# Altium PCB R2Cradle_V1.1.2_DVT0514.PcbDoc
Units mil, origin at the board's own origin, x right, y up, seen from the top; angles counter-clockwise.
Board outline 1575.07 x 1575.04 mil, 4 copper layers (Top Layer, GND, POW, Bottom Layer), stack 127.647 mil thick; 53 components, 13 nets, 144 pads, 79 vias.
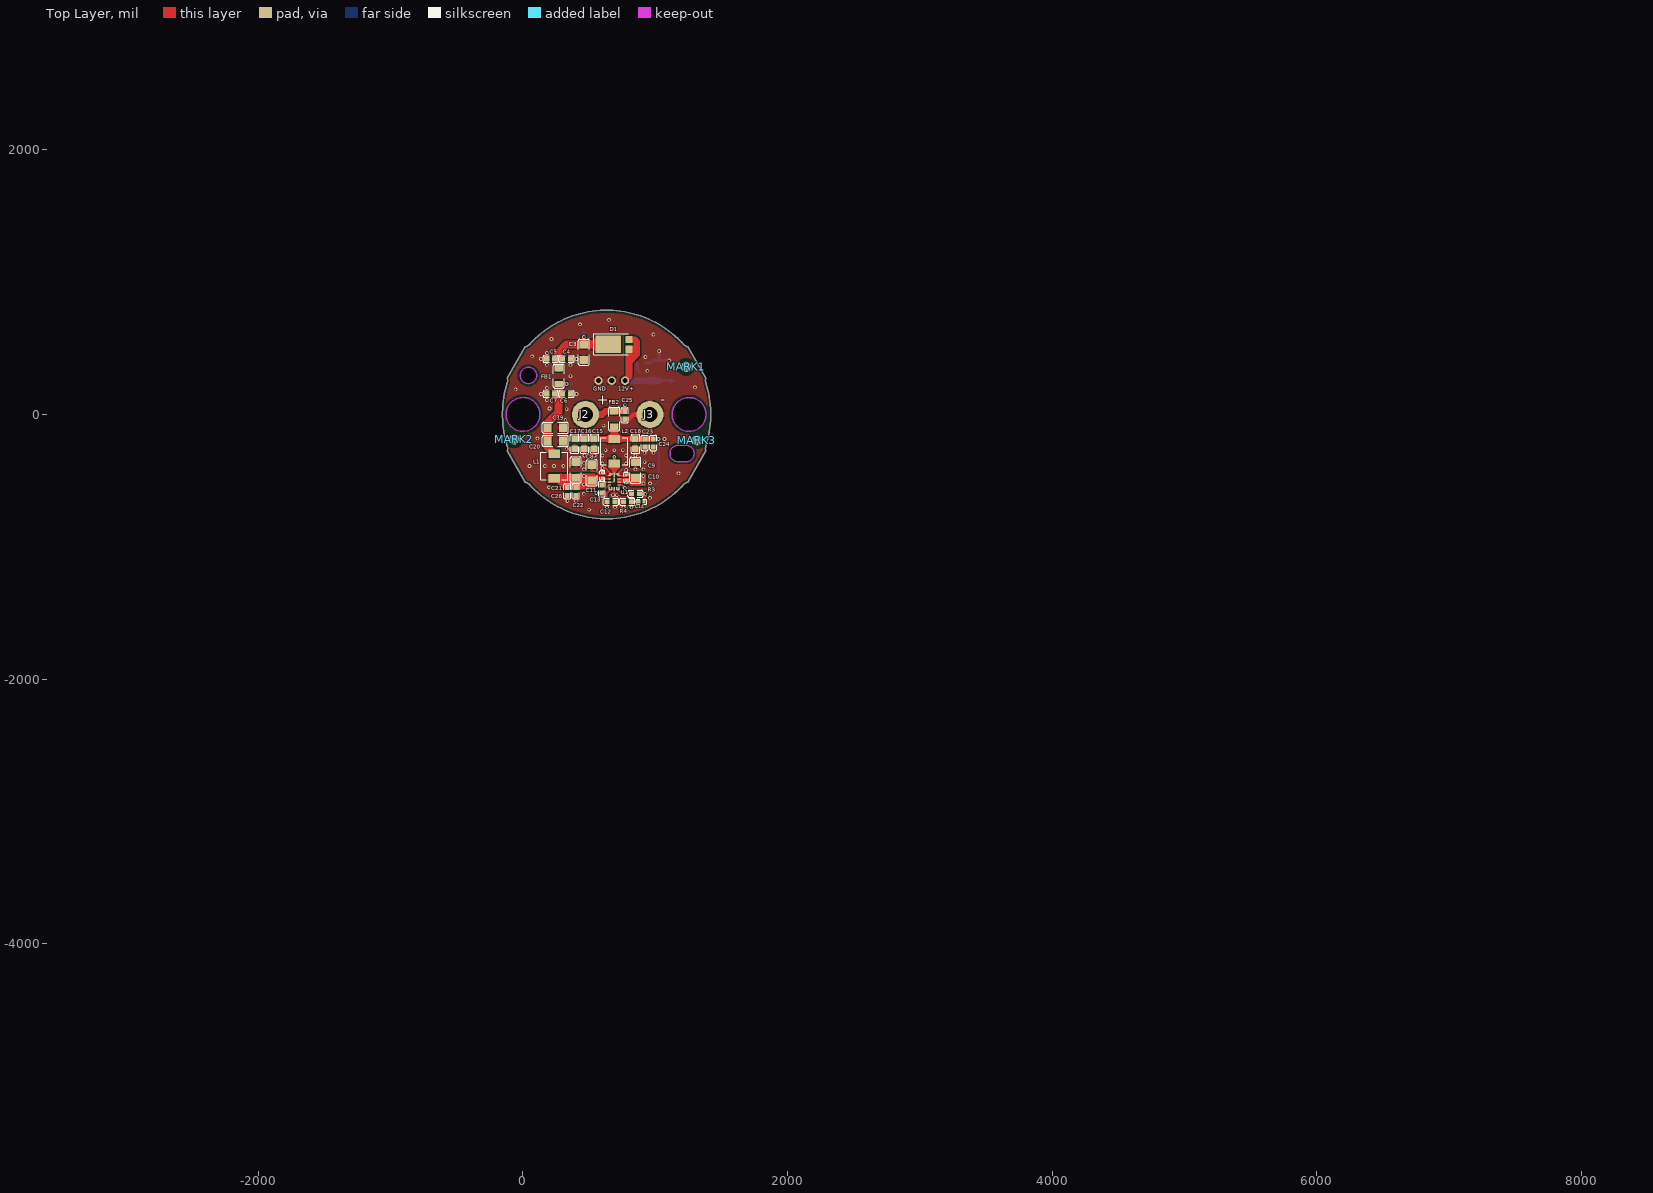
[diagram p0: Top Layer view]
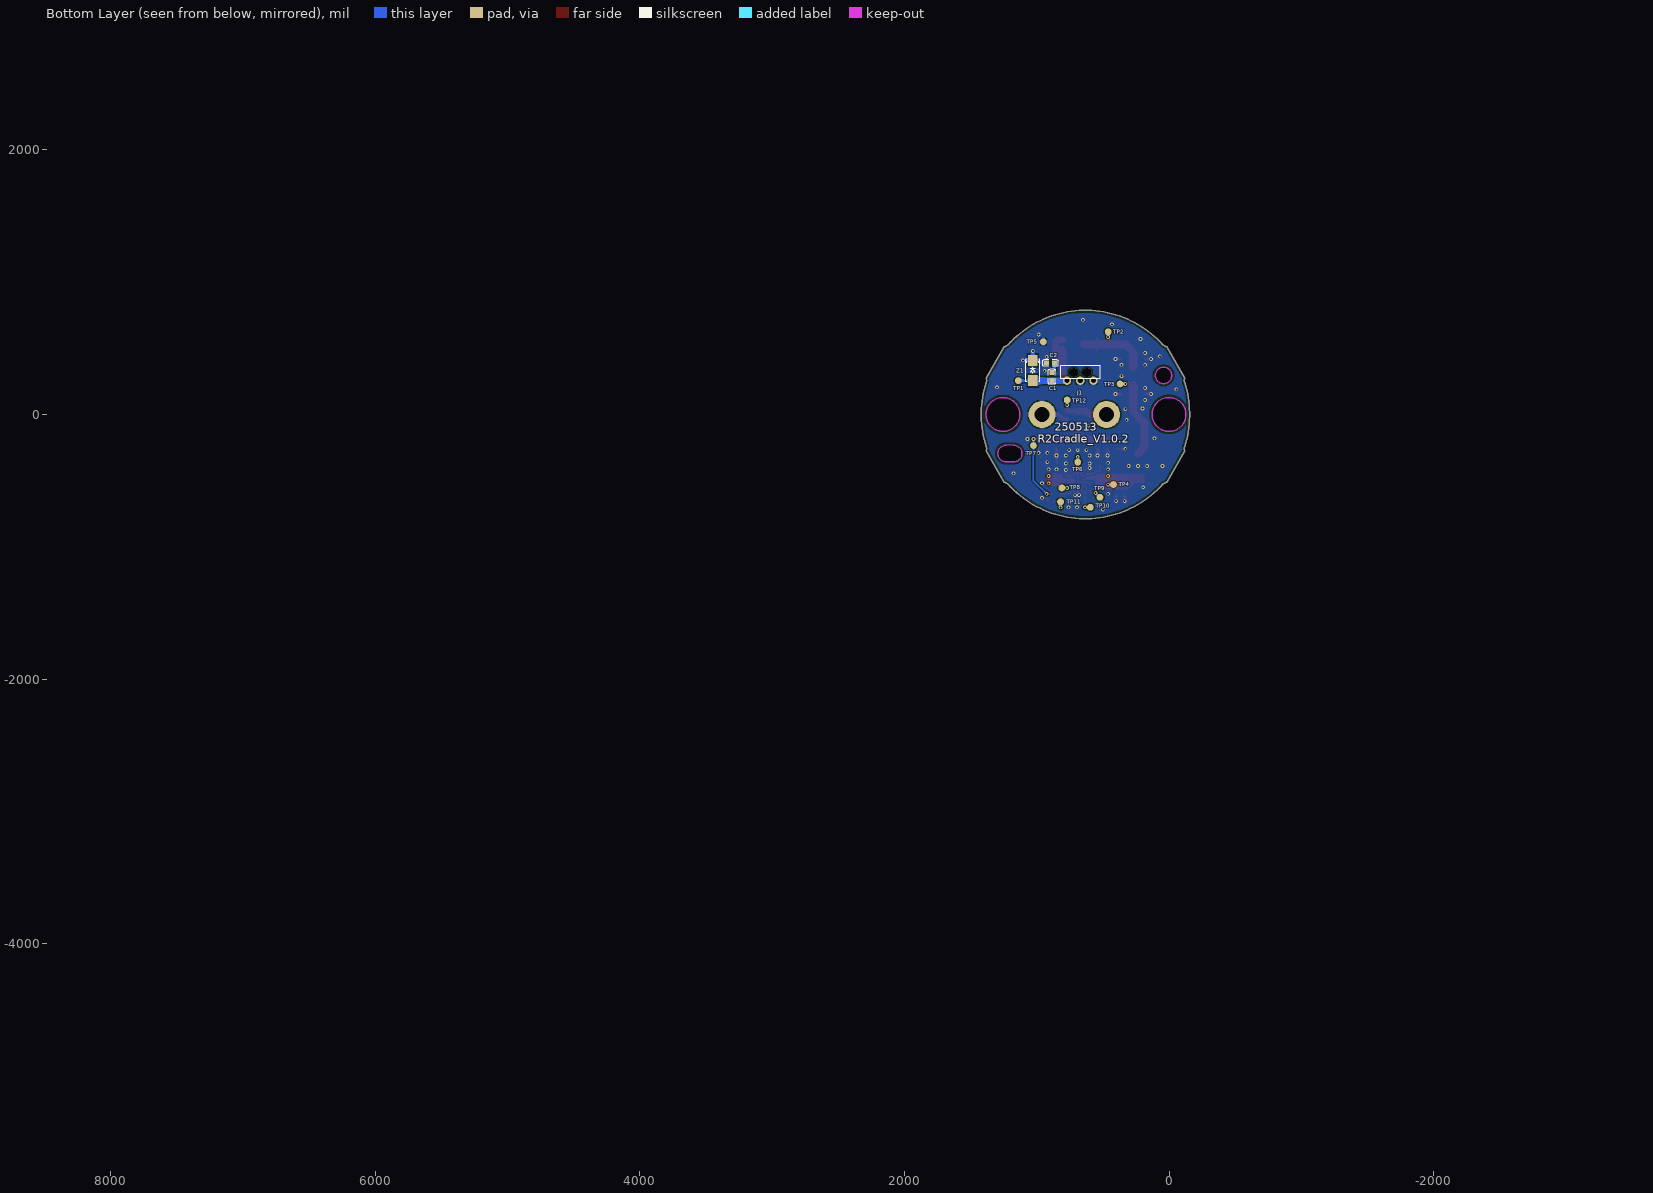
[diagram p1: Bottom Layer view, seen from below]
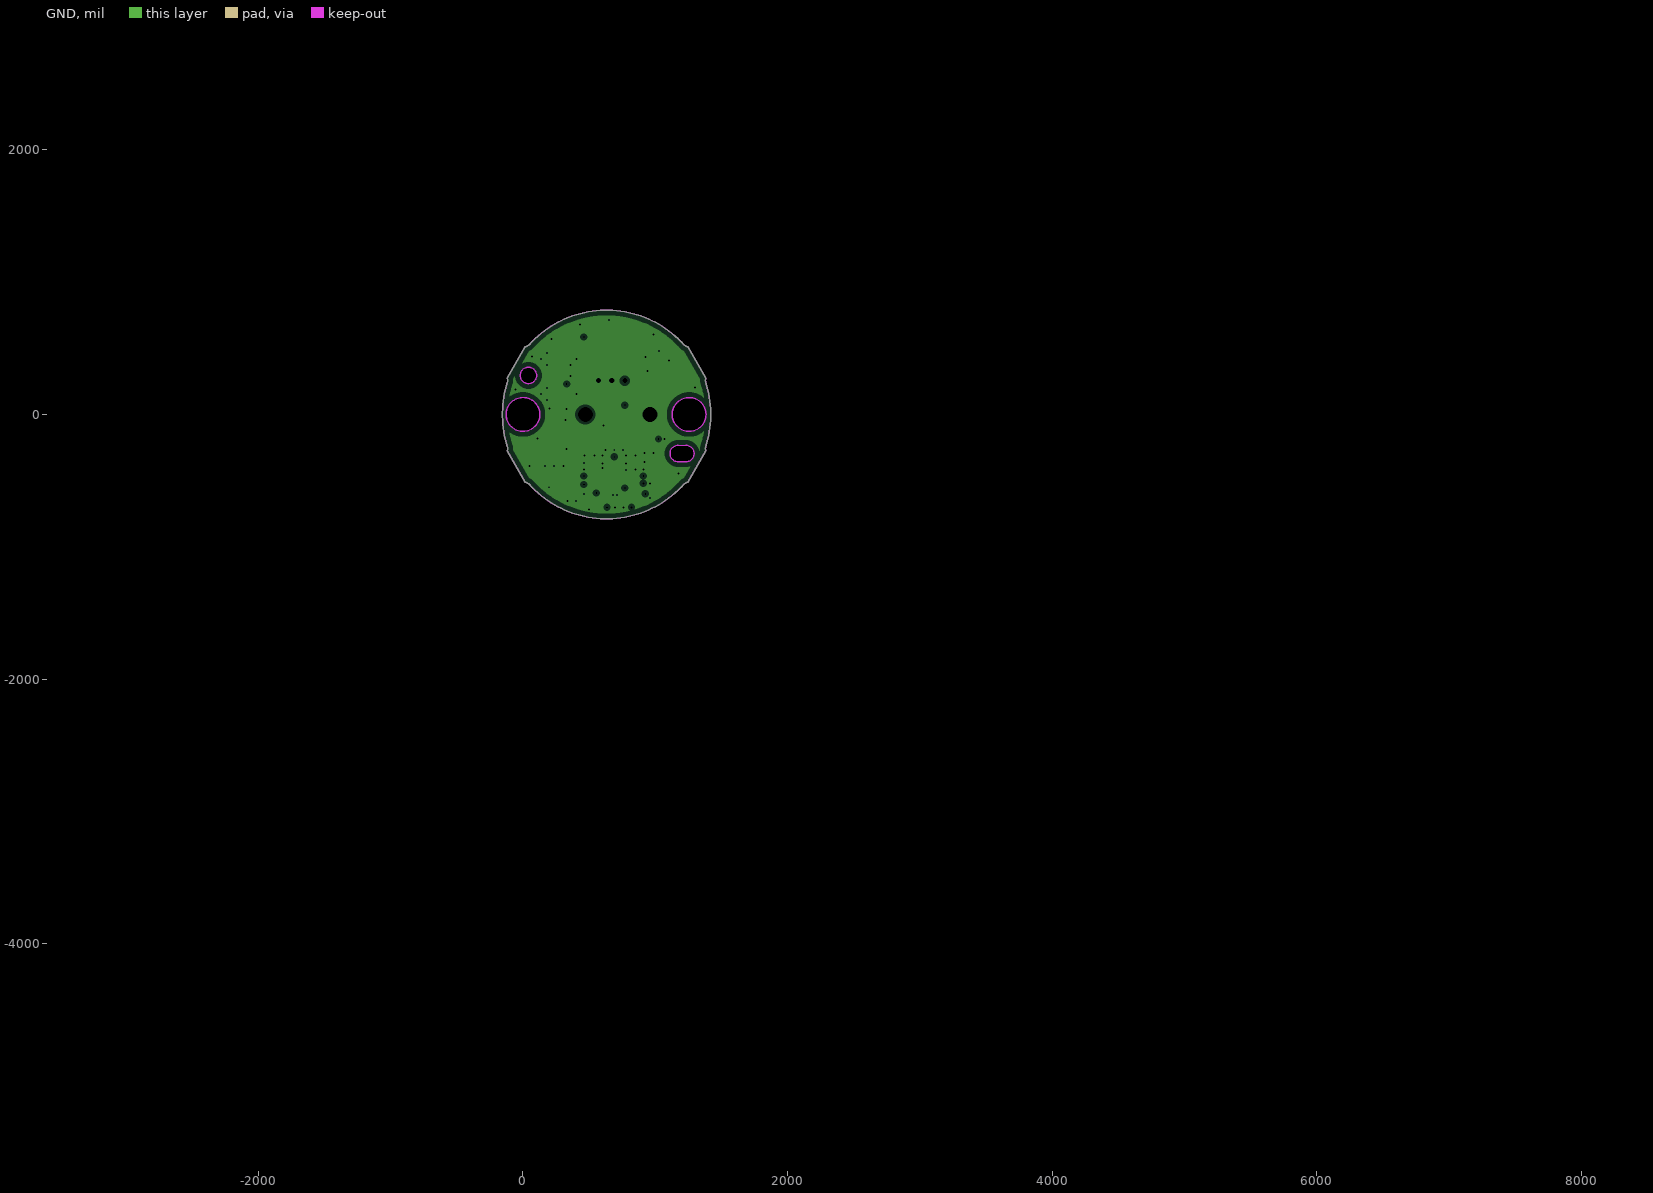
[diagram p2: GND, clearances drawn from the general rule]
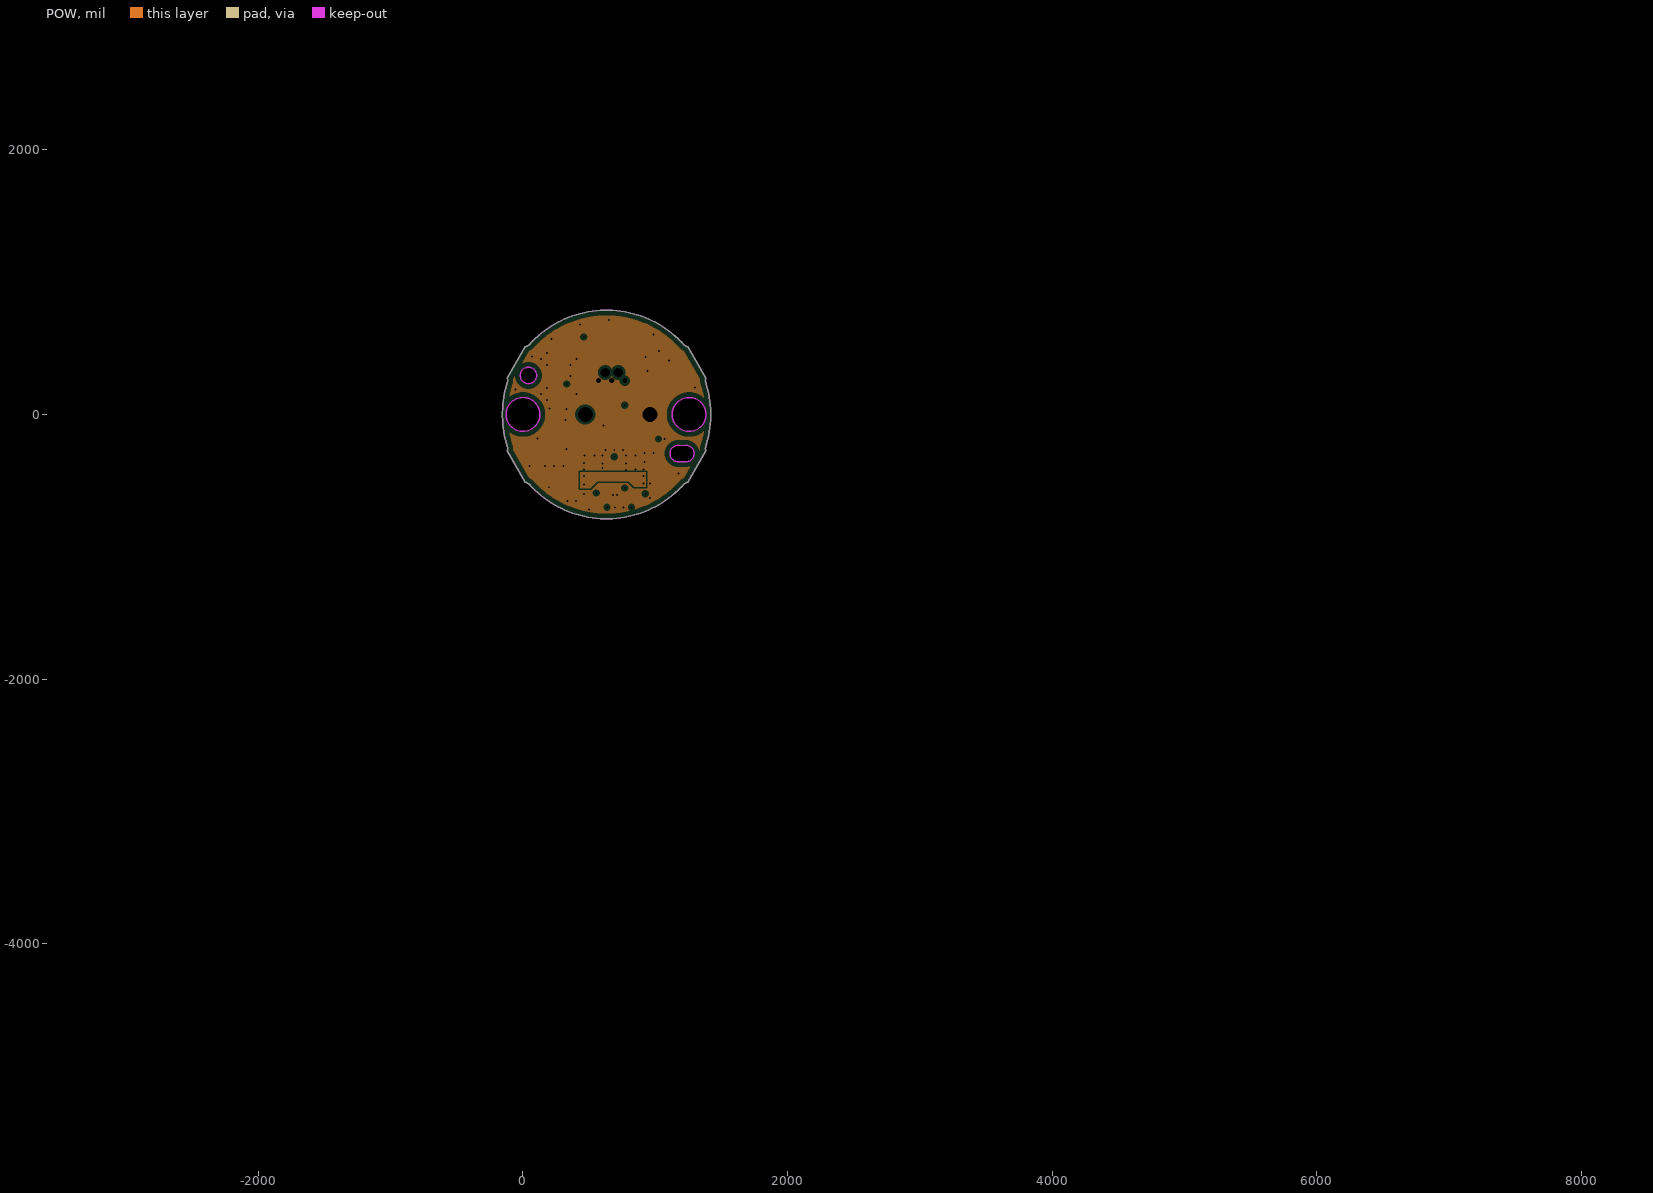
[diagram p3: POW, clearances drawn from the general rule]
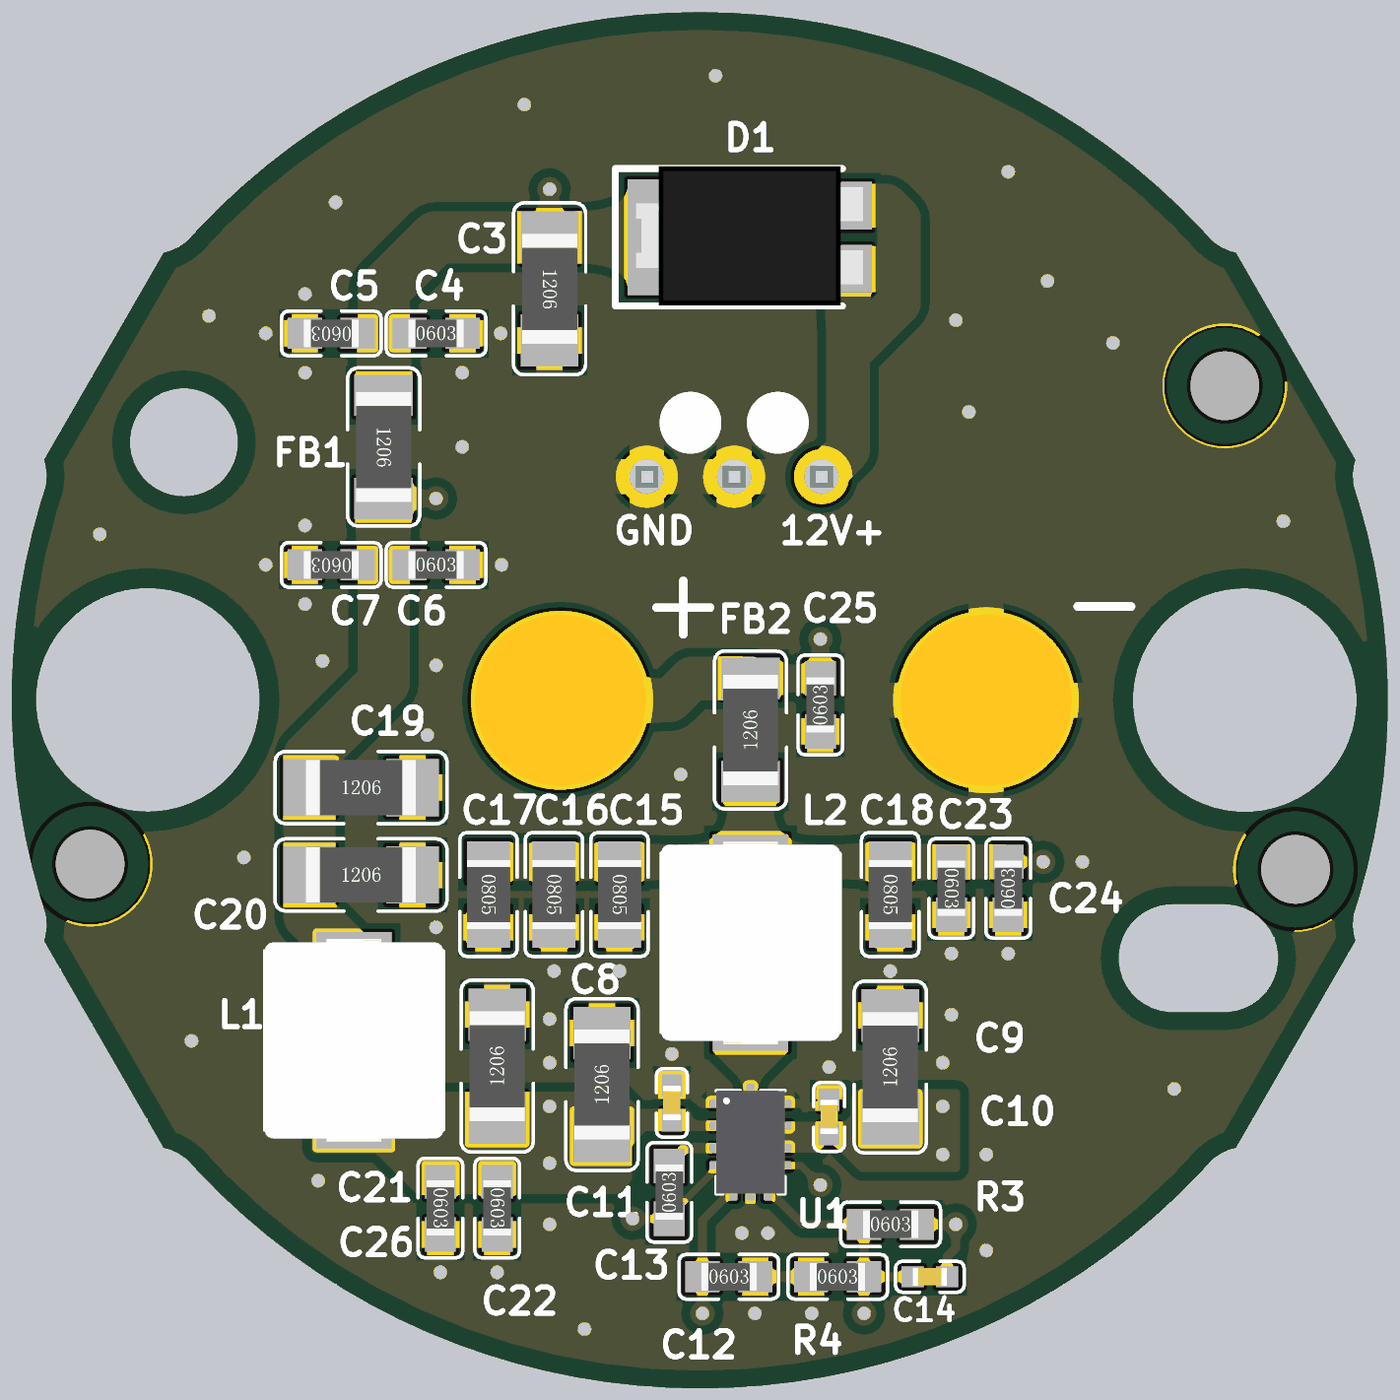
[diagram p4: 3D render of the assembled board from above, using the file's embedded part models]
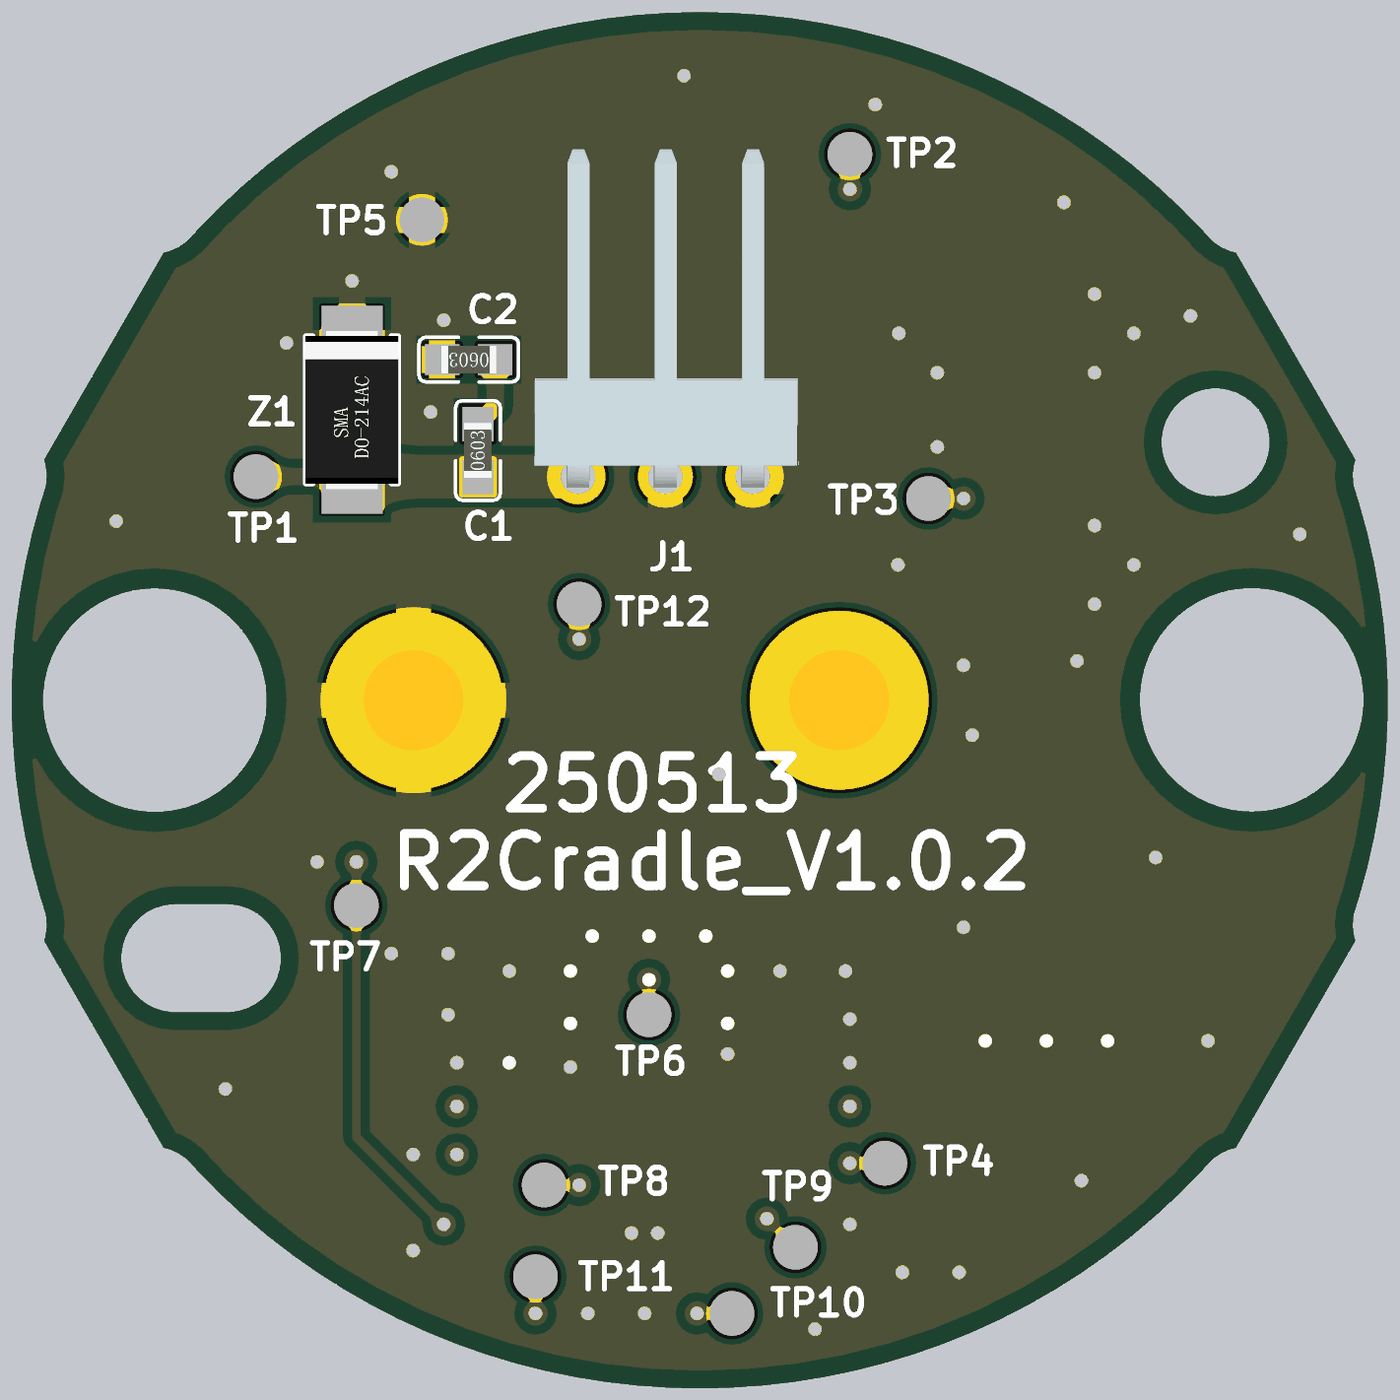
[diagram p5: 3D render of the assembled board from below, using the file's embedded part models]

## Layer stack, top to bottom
Top Solder: solder mask 0.5906, Solder Resist, Dk 3.5
Top Layer: signal copper 2.8
Dielectric 2: prepreg 5, PP-006, Dk 4.1
GND: plane copper 1.3778, net GND_POWER
Dielectric 1: dielectric 109.2913, FR-4, Dk 4.8
POW: plane copper 1.3778, net GND_POWER
Dielectric 3: prepreg 5, PP-006, Dk 4.1
Bottom Layer: signal copper 2.8
Bottom Solder: solder mask 0.5906, Solder Resist, Dk 3.5

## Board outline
-118.67,-275.32 cw(c-118.44,-275.18) -118.7,-275.1 ccw(c-174.55,-256.75) -117.49,-242.57 cw(c631.89,0) -117.49,242.57 ccw(c-174.55,256.75) -118.7,275.1 cw(c-118.44,275.18) -118.67,275.31 18.18,512.35 cw(c18.41,512.22) 18.35,512.48 ccw(c6.32,570.03) 47.13,527.7 cw(c631.89,0) 1216.66,527.7 ccw(c1257.47,570.02) 1245.41,512.48 cw(c1245.38,512.22) 1245.6,512.35 1382.43,275.36 cw(c1382.23,275.19) 1382.48,275.11 ccw(c1438.33,256.75) 1381.28,242.57 cw(c631.9,0) 1381.28,-242.57 ccw(c1438.34,-256.75) 1382.48,-275.09 cw(c1382.23,-275.18) 1382.46,-275.32 1245.6,-512.36 cw(c1245.37,-512.22) 1245.43,-512.48 ccw(c1257.46,-570.02) 1216.66,-527.7 cw(c631.89,0) 47.13,-527.7 ccw(c6.32,-570.02) 18.36,-512.48 cw(c18.41,-512.22) 18.18,-512.35
cut-out: 1173.23,-357.09 cw(c1173.23,-295.28) 1173.23,-233.46 1232.29,-233.46 cw(c1232.29,-295.28) 1232.29,-357.09
cut-out: 41.34,233.46 cw(c41.34,295.28) -20.47,295.28 cw(c41.34,295.28) 41.34,357.09 cw(c41.34,295.28) 103.15,295.28 cw(c41.34,295.28)
cut-out: 1255.81,-127.82 cw(c1255.81,0.13) 1127.86,0.13 cw(c1255.81,0.13) 1255.81,128.08 cw(c1255.81,0.13) 1383.76,0.13 cw(c1255.81,0.13)
cut-out: -0.02,-127.49 cw(c-0.02,0.46) -127.97,0.46 cw(c-0.02,0.46) -0.02,128.41 cw(c-0.02,0.46) 127.93,0.46 cw(c-0.02,0.46)

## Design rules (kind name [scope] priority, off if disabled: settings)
Clearance Clearance_1 [OnLayer('Keep-Out Layer')] p1: gap=10 ignorepadtopadclearanceinfootprint=FALSE except(20: Arc-Fill Arc-Poly Arc-Region Track-Fill Track-Poly Track-Region SMDPad-Fill SMDPad-Poly SMDPad-Region THPad-Fill THPad-Poly THPad-Region Via-Fill Via-Poly Via-Region Fill-Fill Fill-Poly Fill-Region Poly-Poly Poly-Region Region-Region)
Clearance [All] p2: gap=10 ignorepadtopadclearanceinfootprint=FALSE
HoleSize [All] p1: absolutevalues=TRUE maxlimit=200 minlimit=1 maxpercent=80.000 minpercent=20.000
HoleToHoleClearance [All] p1: gap=0 allowstackedmicrovias=TRUE
MinimumSolderMaskSliver [All] p1: minsoldermaskwidth=0
PlaneClearance [All] p1: clearance=20
PlaneConnect [All] p1: planeconnectstyle=Relief reliefexpansion=20 reliefentries=4 reliefconductorwidth=10 reliefairgap=10
PolygonConnect [All] p1: thpad.connectstyle=Relief thpad.reliefconductorwidth=40 thpad.reliefentries=4 thpad.polygonreliefangle="90 Angle" thpad.airgapwidth=10 smdpad.connectstyle=Relief smdpad.reliefconductorwidth=30 smdpad.reliefentries=4 smdpad.polygonreliefangle="90 Angle" smdpad.airgapwidth=10 via.connectstyle=Direct via.reliefconductorwidth=10 via.reliefentries=4 via.polygonreliefangle="90 Angle" via.airgapwidth=10
RoutingVias [All] p1: holewidth=11.81 width=23.62 viastyle="Through Hole" minholewidth=3.94 minwidth=15.75 maxholewidth=23.62 maxwidth=39.37
SilkToSilkClearance [All] p1: silktosilkclearance=0
SilkToSolderMaskClearance [IsPad] p1: minsilkscreentomaskgap=0 clearancetoexposedcopper=TRUE
SolderMaskExpansion [All] p1: expansion=4
Width [All] p1: maxlimit=100 minlimit=5 preferedwidth=10
23 further rules are at their usual default settings.

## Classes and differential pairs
component class R2Cradle_V0.1: C1 C2 C4 C6 C8 C12 C15 C16 C17 C18 C19 C20 C25 D1 J1 J2 J3 L1 L2 MARK1 MARK2 MARK3 R3 R4 TP1 TP2 TP3 TP4 TP5 TP6 TP7 TP8 TP9 TP10 TP11 Z1

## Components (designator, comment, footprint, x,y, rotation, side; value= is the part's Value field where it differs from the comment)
C1 "CAP NP" RC0603 885.83,286 r90 bottom value=103/0603
C2 "CAP NP" RC0603 896.31,390 r0 bottom value=103/0603 (schematic designator C11)
C3 "CAP NP" RC1206 460,470.94 r270 top value=475/1206 (schematic designator C4)
C4 "CAP NP" RC0603 330,420 r0 top value=104/0603 (schematic designator C3)
C5 "CAP NP" RC0603 210,420 r180 top value=104/0603 (schematic designator C3)
C6 "CAP NP" RC0603 330,155 r0 top value=104/0603
C7 "CAP NP" RC0603 210,155 r180 top value=104/0603 (schematic designator C6)
C8 "CAP NP" RC1206 520,-440 r90 top value=475/1206
C9 "CAP NP" RC1206 850,-420 r90 top value=475/1206
C10 "Comment" C0402 780,-477 r90 top
C11 "Comment" C0402 600,-461 r90 top
C12 "CAP NP" RC0603 665.31,-660 r0 top value=105/0603
C13 "CAP NP" RC0603 597,-563.31 r90 top value=105/0603 (schematic designator C12)
C14 "Comment" C0402 895.31,-660 r180 top
C15 "CAP NP" RC0805 465,-222.4 r270 top value=226/0805
C16 "CAP NP" RC0805 540,-222.4 r270 top value=226/0805
C17 "CAP NP" RC0805 390,-222.4 r270 top value=226/0805
C18 "CAP NP" RC0805 850,-222.4 r270 top value=226/0805
C19 "CAP NP" RC1206 244.06,-100 r0 top value=475/1206 (schematic designator C5)
C20 "CAP NP" RC1206 244.06,-200 r0 top value=475/1206 (schematic designator C7)
C21 "CAP NP" RC1206 400,-418.94 r90 top value=475/1206 (schematic designator C7)
C22 "CAP NP" RC0603 400,-581.31 r270 top value=104/0603 (schematic designator C6)
C23 "CAP NP" RC0603 920,-215.32 r270 top value=104/0603 (schematic designator C6)
C24 "NC" RC0603 985,-215.32 r90 top value=NC/0603 (schematic designator R1)
C25 "NC" RC0603 770,-5.31 r90 top value=NC/0603 (schematic designator R1)
C26 "CAP NP" RC0603 335,-581.31 r270 top value=104/0603 (schematic designator C6)
D1 "TD5PS100/TO-277" DPOW 688.98,530 r180 top
FB1 "Comment" N1206 270,290 r270 top
FB2 "Comment" N1206 690,-34.06 r90 top
J1 "CON3" TE1355730-B 671.26,255.91 r0 bottom value=TE1355730
J2 "CON1" pogopin 472.24,0 r0 top value=Pogopin+
J3 "CON1" pogopin 959.64,0 r0 top value=Pogopin-
L1 "INDUCTOR" MDA5030 236,-389.48 r270 top value=4.7uH/MDA5030
L2 "INDUCTOR" MDA5030 690,-277.52 r90 top value=1.5uH/MDA5030
MARK1 "CON1" MARK_2_0#1 1230,360 r90 top
MARK2 "CON1" MARK_2_0#2 -66.04,-187.6 r90 top
MARK3 "CON1" MARK_2_0#3 1291.96,-208.6 r90 top
R3 "R" RC0603 850.31,-600 r0 top value=100K/0603
R4 "R" RC0603 789.68,-660 r0 top value=24.9K/0603
TP1 "TP" MARK_13#1 1155,256 r90 bottom
TP2 "TP" MARK_13#2 460,625 r0 bottom
TP3 "TP" MARK_13#2 370,230.95 r90 bottom
TP4 "TP" MARK_13#2 420,-530 r90 bottom
TP5 "TP" MARK_13#3 950,510 r90 bottom
TP6 "TP" MARK_13#2 690,-360 r90 bottom
TP7 "TP" MARK_13#2 1025,-235 r90 bottom
TP8 "TP" MARK_13#2 810,-555 r90 bottom
TP9 "TP" MARK_13#2 522.31,-626.31 r90 bottom
TP10 "TP" MARK_13#2 595,-702 r90 bottom
TP11 "TP" MARK_13#2 820,-660 r90 bottom
TP12 "TP" MARK_13#2 770,110 r90 bottom (schematic designator TP10)
U1 "Comment" VQFN12 690,-505.94 r0 top
Z1 "TVSbi" SMA 1030,256 r270 bottom value=SMAJ30CA

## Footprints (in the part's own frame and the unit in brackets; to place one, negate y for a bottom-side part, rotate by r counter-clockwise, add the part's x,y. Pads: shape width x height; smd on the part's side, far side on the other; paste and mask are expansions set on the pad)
C0402 [mm] "C?"
  rect 0.65x0.6 smd: 1(-0.5,0) 2(0.5,0)
  silkscreen extent -1,-0.45 1,0.45, body extent -0.59,-0.26 0.6,0.26, height 0.51
DPOW [mm] "D?"
  rect 1.4x1.39 smd: 1(-2.862,-0.92) 1(-2.862,0.92)
  rect 4.86x3.36 smd: 2(1.12,0)
  silkscreen extent -2.7,-2 3.9,2, body extent -3.3,-2.07 3.3,1.98, height 1.18
MARK_2_0#1 [mm] "MARK?"
  round 2 smd: 1(0,-0.076)
MARK_2_0#2 [mm] "MARK?"
  round 2 smd: 1(0,0)
MARK_2_0#3 [mm] "MARK?"
  round 2 smd: 1(0.381,-0.559)
MARK_13#1 [mm] "J?"
  round 1.3 smd: 1(0,-0.381)
MARK_13#2 [mm] "J?"
  round 1.3 smd: 1(0,0)
MARK_13#3 [mm] "J?"
  round 1.3 smd: 1(1.016,0)
MDA5030 [mm] "L?"
  rect 1.6x2.2 smd: 1(-2.35,0) 2(2.35,0)
  silkscreen extent -2.6,-2.6 2.6,2.6, body extent -2.95,-2.6 2.95,2.6, height 2.91
N1206 [mm] "RC?"
  rect 1.2x1.7 smd: 1(-1.5,0) 2(1.5,0)
  silkscreen extent -2.3,-1.05 2.3,1.05, body extent -1.6,-0.8 1.6,0.8, height 0.6
pogopin [mm]
  round 5.2 hole 2.9: 1(0,0)
  body extent -2.5,-2.5 2.5,2.5, height 16.55
RC0603 [mm] "RC?"
  rect 1x0.9 smd: 1(-0.77,0) 2(0.77,0)
  silkscreen extent -1.45,-0.65 1.45,0.65, body extent -0.8,-0.4 0.8,0.4, height 0.45
RC0805 [mm] "RC?"
  rect 1.2x1.25 smd: 1(-0.95,0) 2(0.95,0)
  silkscreen extent -1.8,-0.83 1.8,0.83, body extent -1,-0.63 1,0.63, height 0.55
RC1206 [mm] "RC?"
  rect 1.52x1.67 smd: 1(-1.5,0) 2(1.5,0)
  silkscreen extent -2.5,-1.05 2.5,1.05, body extent -1.6,-0.8 1.6,0.8, height 0.6
SMA [mil] "D?"
  rect 85x70 smd mask+2.5: 1(0,0) 2(-153,0)
  silkscreen extent -161,-53 8,53, body extent -167,-53 14,53, height 95
TE1355730-B [mm] "J?"
  round 1.6 hole 1: 1(-2.54,0) 2(0,0) 3(2.54,0)
  round 1.8 on Top Overlay: ""(-1.27,-1.57) ""(1.27,-1.57)
  silkscreen extent -3.86,-2.85 3.79,-0.34, body extent -3.83,-9.52 3.81,0.32, height 3.28
VQFN12 [mm] "U?"
  rrect50% 0.6x0.25 smd: 1(-0.9,1.125) 2(-0.9,0.475) 3(-0.9,-0.175) 4(-0.9,-0.675) 8(0.9,-0.675) 9(0.9,-0.175) 10(0.9,0.475) 11(0.9,1.125)
  rrect50% 0.25x0.6 smd: 5(-0.5,-1.4) 6(0,-1.4) 7(0.5,-1.4)
  rrect50% 0.25x0.812 smd: 12(0,0.282) 12(0,1.294)
  silkscreen extent -1,-1.5 1,1.5, body extent -1.02,-1.52 1.02,1.52, height 0.8

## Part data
C24 C25: library part R, "100K/0603"
D1: library part D1

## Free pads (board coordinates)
  round 10 on Mech2: 1(-3404.68,-5516.68) 1(-3404.68,-5516.68) 1(-3404.68,2751.03) 1(-3404.68,2751.03) 1(-3207.83,-5319.83) 1(-3207.83,-5319.83) 1(-3207.83,2554.18) 1(-3207.83,2554.18) 1(1004.77,-5319.83) 1(2185.87,-5319.83) 1(2185.87,-4926.13) 1(2185.87,-4532.43) 1(2185.87,-4138.73) 1(2185.87,-3745.03) 1(2185.87,-2957.63) 1(2185.87,-2957.63) 1(2776.42,-5319.83) 1(2776.42,-3745.03) 1(3760.67,-5319.83) 1(3760.67,-2957.63) 1(4154.37,-5319.83) 1(4154.37,-3745.03) 1(5138.63,-5319.83) 1(5138.63,-3745.03) 1(6122.88,-4926.13) 1(6122.88,-4138.73) 1(6122.88,-5319.83) 1(6122.88,-2957.63) 1(8091.38,-5319.83) 1(8091.38,-5319.83) 1(8091.38,-5319.83) 1(8091.38,-4532.43) 1(8091.38,-3745.03) 1(8091.38,-2957.63) 1(8091.38,2554.18) 1(8091.38,2554.18) 1(8288.23,-5516.68) 1(8288.23,-5516.68) 1(8288.23,2751.03) 1(8288.23,2751.03)

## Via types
v1: diameter 28, hole 15, Top Layer to Bottom Layer, tented both sides, 77 vias
v2: diameter 70.87, hole 70.87, POW to Bottom Layer, 2 vias

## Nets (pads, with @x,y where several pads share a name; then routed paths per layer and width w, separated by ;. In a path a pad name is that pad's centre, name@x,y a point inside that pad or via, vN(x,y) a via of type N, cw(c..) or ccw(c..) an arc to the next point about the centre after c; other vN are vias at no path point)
12V: C8.1 C9.1 C10.1 C11.1 C21.1 C22.1 C26.1 L1.2 TP4.1 U1.2 U1.9 U1.10 | length 1716.5
  Top Layer w10: U1.10@717,-487.24 717,-512.8 725.43,-512.8 764.83,-512.83 777,-500.67 780,-500.67 C10.1@780,-499.68 ; U1.10@717,-487.2 725.43,-487.21 780,-487.23 800,-487.24 810,-477.24 810,-455 815,-450 925,-450 925,-535 818.31,-535 C10.1
  Top Layer w12: C8.1@519.98,-473.97 561.34,-473.93 ; C11.1@605,-474 616.09,-473.88 ; 631,-487.2 cw(c631,-472.2) 616.09,-473.88 ; U1.2 567.24,-487.24 548.27,-506.22 548.27,-546.73 535.51,-559.49 444.54,-559.49 406.42,-559.53 400.01,-559.53 340.97,-559.59 337.06,-560.44 311.35,-560.44 263.84,-512.93 236.03,-512.96 193.06,-513 193.03,-482.04 193,-454.16 235.97,-454.12 397.98,-453.97 399.98,-453.96 459.98,-453.91 541.2,-453.83 553.19,-465.8 561.34,-473.93 ; 561.34,-473.93 599.99,-473.89 616.09,-473.88
  Bottom Layer w10: TP4.1 v1(460,-530)
  other v1: 910,-520 460,-465 910,-465
GND_POWER: C2.2 C3.2 C4.2 C5.2 C6.2 C7.2 C8.2 C9.2 C10.2 C11.2 C12.2 C15.2 C16.2 C17.2 C18.2 C19.2 C20.2 C21.2 C22.2 C23.2 C24.1 C25.1 C26.2 J1.1 J1.2 J3.1 R4.1 TP5.1 U1.1 U1.6 U1.11 Z1.2 | length 1723.6
  Top Layer w10: C8.2 520,-425 525,-430 555,-430 574,-449 622,-449 634.65,-461.65 U1.1 665,-461.65 665,-445 625,-405 v1(600,-405) ; 750,-410 715,-445 715,-461.65 U1.11 749.65,-461.65 753,-465 C10.2@780,-465
  Top Layer w12: U1.6 690,-596 696.82,-602.82 C12.2@696.82,-660 ; C12.2 R4.1 ; C10.2 v1(780,-420) ; v1(920,-290) C23.2 ; v1(985,-290) C24.1
  Top Layer w20: v1(135,155) C7.2 ; v1(135,420) C5.2 ; v1(330,-260) 330.1,-259.9 389.9,-259.9 C17.2 ; v1(335,-655) C26.2 ; C6.2 v1(405,155) ; C4.2 v1(404,420) ; v1(400,-655) C22.2 ; v1(465,-310) C15.2 ; v1(540,-310) C16.2 C16.2@540.1,-259.9 ; C9.2 v1(850,-310) C18.2
  Top Layer w30: C25.1 801.37,-35.63 837,0 J3.1
  Bottom Layer w20: C2.2 964.5,390 983.5,409 Z1.2 ; Z1.2@1023.5,402.5 Z1.2 ; v1(1030,480) Z1.2 ; v1(1105,409) Z1.2
  other v1: 500,-720 695,-702 760,-702 960,-630 680,-610 710,-610 460,-600 195,-550 960,-520 1175,-445 460,-415 850,-415 910,-415 50,-390 165,-390 235,-390 305,-390 600,-370 780,-370 460,-365 920,-360 600,-310 780,-310 625,-270 690,-270 755,-270 1070,-185 110,-180 610,-85 320,-40 330,40 200,45 180,110 -55,190 180,200 1300,205 360,290 940,330 180,375 360,375 925,435 70,440 180,465 215,570 985,605 431,682 650,715
NetC1_1: C1.1 D1.1 J1.3 TP1.1 Z1.1 | length 926.1
  Top Layer w40: J1.3 J1.3@771.26,262.13
  Top Layer w50: J1.3 801.65,286.3 801.65,493.78 860,493.78 ; D1.1@801.65,566.22 845,566.22 860,551.22 860,493.78 ; 802.38,397.38 860,455 860,493.78
  Bottom Layer w20: Z1.1 TP1.1
  Bottom Layer w40: J1.3 J1.3@771.31,255.95 ; Z1.1@1029.95,255.95 Z1.1
  Bottom Layer w50: J1.3@771.31,255.95 Z1.1@1029.95,255.95
NetC1_2: C1.2 C2.1 | length 81.9
  Bottom Layer w20: C2.1 866,336.14 C1.2
NetC3_1: C3.1 C4.1 C5.1 D1.2 FB1.1 TP2.1 | length 608.7
  Top Layer w20: C3.1 v1(460,585)
  Top Layer w60: FB1.1@270,356 270,470 330,530 C3.1 D1.2
  Bottom Layer w20: v1(460,585) TP2.1
NetC5_1: C6.1 C7.1 C19.1 C20.1 FB1.2 L1.1 TP3.1 | length 676.3
  Top Layer w20: FB1.2 v1(330,230.95)
  Top Layer w60: L1.1 185,-245.96 C20.1 C19.1 185,-64.57 270,20.43 FB1.2@270,223
  Bottom Layer w20: v1(330,230.95) TP3.1
NetC12_1: C12.1 TP10.1 U1.5 | length 195.5
  Top Layer w10: v1(635,-702) C12.1 635,-595 U1.5@669.32,-560.68
  Bottom Layer w10: TP10.1 v1(635,-702)
NetC13_1: C13.1 TP9.1 U1.4 | length 170.3
  Top Layer w8: v1(555,-593.63) 593.27,-593.63 U1.4@653.96,-532.94
  Bottom Layer w8: TP9.1 v1(555,-593.63)
NetC13_2: C13.2 L2.1 TP6.1 U1.3 U1.12 | length 422.7
  Top Layer w10: L2.1@671.5,-347 690,-365.5 v1(690,-320) ; L2.1@718,-386 L2.1@728,-386
  Top Layer w12: C13.2 597,-531.03 615.2,-512.83 U1.3 683.17,-512.83 U1.12@690,-506
  Top Layer w15: L2.1@655,-389 655,-400 690,-435 ; U1.12@690,-506 690,-494.84 690,-455 690,-435 ; L2.1@725,-394 725,-400 690,-435
  Bottom Layer w8: TP6.1@694,-357.96 TP6.1@702.26,-366.22
  Bottom Layer w10: TP6.1@690,-357 v1(690,-320)
NetC14_1: C14.1 C15.1 C16.1 C17.1 C18.1 C23.1 C24.2 FB2.1 L2.2 R3.2 TP7.1 | length 1257.9
  Top Layer w10: R3.2 v1(925,-600) 925,-627 915,-637 C14.1 ; C24.2 v1(1025,-185)
  Top Layer w40: C17.1@412,-185 C16.1 L2.2 C18.1 C23.1 C24.2@980,-185
  Top Layer w50: L2.2 FB2.1@690,-100
  Bottom Layer w10: v1(925,-600) 1025,-500 TP7.1 v1(1025,-185)
NetC14_2: C14.2 R3.1 R4.2 TP11.1 U1.7 | length 324.4
  Top Layer w10: U1.7@710.32,-560.68 749.64,-600 R3.1@818.82,-600 ; v1(820,-702) R4.2 ; R3.1 R4.2 ; C14.2 R4.2
  Bottom Layer w10: v1(820,-702) TP11.1
NetJ2_1: C25.2 FB2.2 J2.1 TP12.1 | length 416.3
  Top Layer w20: C25.2 v1(770,70)
  Top Layer w30: J2.1@516,0 J2.1@532.38,16.38 ; FB2.2 C25.2
  Top Layer w50: J2.1 516,0 598,0 623,25 FB2.2
  Bottom Layer w20: v1(770,70) TP12.1
NetR2_1: TP8.1 U1.8 | length 93.9
  Top Layer w8: U1.8 747.52,-532.52 v1(770,-555)
  Bottom Layer w8: v1(770,-555) TP8.1
pads on no net: J1. MARK1.1 MARK2.1 MARK3.1
copper on no net:
  other v2: 621.26,317.72 721.26,317.72

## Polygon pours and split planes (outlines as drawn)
GND_POWER on Bottom Layer "GND_POWER_L04_P000" (solid, remove dead copper, pour order 0): -232,857 1481.84,857 1481.84,-874 -232,-874
GND_POWER on Top Layer "GND_POWER_L01_P001" (solid, remove dead copper, pour order 1): -235.03,843.44 1483.81,843.44 1483.81,-858.56 -235.03,-858.56
GND_POWER on GND (split plane): 856 vertices, not listed, extent -104.2,-747.58 1369.12,747.58
12V on POW (split plane): 929.9,-547.8 838.33,-547.8 799.72,-509.19 798.06,-508.09 796.11,-507.7 564.2,-507.7 562.25,-508.09 560.6,-509.19 509.9,-559.89 430.1,-559.89 430.1,-435.1 929.9,-435.1
GND_POWER on POW (split plane): 856 vertices, not listed, extent -104.2,-747.58 1369.12,747.58

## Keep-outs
Keep-Out Layer:
  circle w0.39: c41.34,295.28 r61.81
  circle w5: c-0.02,0.46 r127.95
  circle w5: c1255.81,0.13 r127.95
  lines w0.39: 1245.6,-512.36 cw(c1245.37,-512.22) 1245.43,-512.48 ccw(c1257.46,-570.03) 1216.66,-527.7 cw(c631.89,0) 47.13,-527.7 ccw(c6.32,-570.03) 18.36,-512.48 cw(c18.41,-512.22) 18.18,-512.35 -118.67,-275.32 cw(c-118.44,-275.18) -118.7,-275.1 ccw(c-174.55,-256.75) -117.49,-242.57 cw(c631.89,0) -117.49,242.57 ccw(c-174.55,256.75) -118.7,275.1 cw(c-118.44,275.18) -118.67,275.31 18.18,512.35 cw(c18.41,512.22) 18.35,512.48 ccw(c6.32,570.03) 47.13,527.7 cw(c631.89,0) 1216.66,527.7 ccw(c1257.46,570.02) 1245.41,512.48 cw(c1245.37,512.22) 1245.6,512.35 1382.43,275.36 cw(c1382.23,275.19) 1382.48,275.11 ccw(c1438.33,256.75) 1381.28,242.57 cw(c631.89,0) 1381.28,-242.57 ccw(c1438.33,-256.75) 1382.48,-275.09 cw(c1382.23,-275.18) 1382.46,-275.32 1245.6,-512.36 ; 1173.23,-357.09 cw(c1173.23,-295.28) 1173.23,-233.46 1232.29,-233.46 cw(c1232.29,-295.28) 1232.29,-357.09 1173.23,-357.09

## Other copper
Top Layer:
  pour cut-out: 1314.52,-263.07 cw(c1314.52,-194.18) 1245.62,-194.18 cw(c1314.52,-194.18) 1314.52,-125.28 cw(c1314.52,-194.18) 1383.42,-194.18 cw(c1314.52,-194.18)
  pour cut-out: -66.04,-256.5 cw(c-66.04,-187.6) -134.94,-187.6 cw(c-66.04,-187.6) -66.04,-118.7 cw(c-66.04,-187.6) 2.86,-187.6 cw(c-66.04,-187.6)
  pour cut-out: 1232.63,290.76 cw(c1232.63,359.65) 1163.74,359.65 cw(c1232.63,359.65) 1232.63,428.55 cw(c1232.63,359.65) 1301.53,359.65 cw(c1232.63,359.65)
  region net 12V: 535.55,-559.45 548.27,-546.73 548.27,-506.22 570.07,-484.42 599.99,-484.42 599.99,-473.89 561.3,-473.93 541.2,-453.83 193,-454.16 193,-512.94 263.94,-512.93 310.58,-559.58
  region net 12V: 925,-535 925,-450 815,-450 810,-455 810,-477.24 800,-487.24 717,-487.24 717,-512.83 765.82,-512.83 780,-498.65 816.35,-535
  region net NetC13_2: 690,-435 725,-400 725,-388 655,-388 655,-400
POW (plane layer: these items are gaps in the copper):
  lines w10: 425,-564.99 425,-430 935,-430 935,-552.9 836.22,-552.9 796.11,-512.8 564.2,-512.8 512.01,-564.99 425,-564.99

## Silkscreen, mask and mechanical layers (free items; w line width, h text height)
Top Overlay:
  text "GND" at 530,180 h30
  text "12V+" at 720,180 h30
  text "-" at 1038.96,76.41 h80
  text "+" at 556.96,75.07 h80
Bottom Overlay:
  text "250513" at 864,-124 h60
  text "R2Cradle_V1.0.2" at 991,-213 h60
Top Solder:
  circle w5: c1313.96,-193.6 r68.9
  circle w5: c-66.04,-187.6 r68.9
  circle w5: c1233,360 r68.9
Mechanical 2:
  lines w0.5: 552.88,788.4 cw(c626.02,4.14) 699.17,788.4 ; 614.48,-56.69 614.48,57.09 ; 626.22,-76.37 637.64,-76.37 ; 626.22,76.78 637.64,76.78 ; 649.38,-56.69 649.38,57.09 ; 8079.55,3676.75 cw(c8259.65,3636.41) 8087.72,3703.52 ; 614.48,-76.37 614.48,76.78 649.38,76.78 649.38,-76.37 614.48,-76.37
  lines w20: 1004.77,-5319.83 8091.38,-5319.83 ; 2185.87,-5319.83 2185.87,-2957.63 8091.38,-2957.63 ; 2185.87,-4926.13 6122.88,-4926.13 ; 2185.87,-4532.43 8091.38,-4532.43 ; 2185.87,-4138.73 6122.88,-4138.73 ; 2185.87,-3745.03 8091.38,-3745.03 ; 2776.42,-5319.83 2776.42,-3745.03 ; 3760.67,-5319.83 3760.67,-2957.63 ; 4154.37,-5319.83 4154.37,-3745.03 ; 5138.63,-5319.83 5138.63,-3745.03 ; 6122.88,-5319.83 6122.88,-2957.63 ; 8091.38,-5319.83 8091.38,2554.18 -3207.83,2554.18 -3207.83,-5319.83 8091.38,-5319.83 ; -3404.68,-5516.68 8288.23,-5516.68 8288.23,2751.03 -3404.68,2751.03 -3404.68,-5516.68
  text "技术要求：" at 5630.5,-1193.54 h200
  text "1、板材：FR4/Tg150C" at 5635.32,-1384.11 h200
  text "2、板厚：3.2mm±0.15mm" at 5635.13,-1597.8 h200
  text "3、层数：4" at 5630.32,-1788.54 h200
  text "4、铜箔厚度：1.5oz/1oz" at 5630.32,-1978.54 h200
  text "5、表面处理：沉金" at 5630.32,-2169.28 h200
  text "6、阻焊油墨颜色：绿色" at 5625.32,-2353.54 h200
  text "7、丝印颜色：白色" at 5630.32,-2528.54 h200
  text "8、过孔处理：塞孔处理" at 5620.2,-2740.92 h200
  text "制造要求" at -2635.14,-3266.3 h180
  text "上海岱美汽车内饰件" at 6294.32,-3340.32 h180
  text "成品印刷板：" at -2644.68,-3439.69 h180
  text "PCB" at 4617.3,-3456.63 h200
  text "有限公司" at 6695.49,-3571.02 h180
  text "必须满足IPC-6012第3.2节中材料选择、" at -2644.51,-3589.69 h180
  text "最终表面镀层和涂层厚度的要求，" at -2644.68,-3739.69 h180
  text "并符合第3.3.1-3.3.9节的要求，以获得均匀一致的板材质量。" at -2644.68,-3879.69 h180
  text "产品名称：" at 6167.47,-3972.36 h180
  text "日期" at 5430.5,-3994.28 h200
  text "按照第3.3节中的程序进行100%目视检查。" at -2644.68,-4010.36 h180
  text "签名" at 4470.5,-4022.06 h200
  text "板尺寸：" at -2644.51,-4164.69 h180
  text "Cargolamp" at 6583.3,-4231.08 h100
  text "符合IPC-6012第3.4节关于板的尺寸要求。" at -2644.68,-4299.69 h180
  text "PCB版本" at 2225.32,-4362.52 h150
  text "制作" at 3825.47,-4367.76 h160
  text "V1.0" at 2924.01,-4409.34 h200
  text "请参见表4-3。每个生产批次的验收测试和频率。" at -2644.68,-4440.36 h180
  text "污染：" at -2644.68,-4581.02 h180
  text "ERP：" at 6192.3,-4751.19 h180
  text "根据IPC-6012第3.9节的规定，在涂覆涂层之前，" at -2644.51,-4760.36 h180
  text "审核" at 3830.47,-4782.76 h160
  text "比例" at 2330.5,-4789.84 h200
  text "1:1" at 3006.34,-4817.71 h200
  text "未涂覆的板材必须在离子和其他污染物的允许范围内。" at -2644.51,-4899.69 h180
  text "无" at 6712.3,-5034.26 h180
  text "未涂层和成品印刷板以及流行的印刷电路板组件的污染水平" at -2644.51,-5039.69 h180
  text "必须小于1.56ug/cm2的氯化钠当量。" at -2644.51,-5171.62 h180
  text "批准" at 3830.32,-5173.2 h160
Mechanical 3:
  drawing of 157 lines, arcs and shapes, not listed
Mechanical 13:
  circle w0.39: c0,0 r127.95
  circle w0.39: c0,0 r130.15
  circle w0.39: c472.24,0 r53.15
  circle w0.39: c472.24,0 r98.43
  circle w0.39: c472.24,0 r39.37
  circle w0.39: c41.34,295.28 r64.01
  circle w0.39: c571.26,255.91 r25.59
  circle w0.39: c671.26,255.91 r25.59
  circle w0.39: c771.26,255.91 r25.59
  circle w0.39: c959.64,0 r39.37
  circle w0.39: c959.64,0 r98.43
  circle w0.39: c959.65,0 r53.15
  circle w0.39: c1255.91,0 r130.15
  circle w0.39: c1255.91,0 r127.95
  lines w0.39: 548.99,268.51 558.65,268.51 ; 593.53,268.51 583.85,268.51 ; 648.99,268.51 658.66,268.51 ; 693.53,268.51 683.85,268.51 ; 748.99,268.51 758.65,268.51 ; 793.53,268.51 783.85,268.51 ; 1173.23,-357.09 1173.23,-359.29 ; 1173.23,-233.46 1173.23,-231.27 ; 1232.29,-357.09 1232.29,-359.29 ; 1232.29,-233.46 1232.29,-231.27 ; 558.65,243.32 583.85,243.32 ; 558.65,243.32 558.65,268.51 ; 558.65,243.32 564.39,249.05 ; 558.65,268.51 564.39,262.78 ; 558.65,268.51 583.85,268.51 ; 564.39,249.05 564.39,262.78 ; 564.39,249.05 578.12,249.05 ; 564.39,262.78 578.12,262.78 ; 578.12,249.05 578.12,262.78 ; 578.12,249.05 583.85,243.32 ; 578.12,262.78 583.85,268.51 ; 583.85,243.32 583.85,268.51 ; 658.66,243.32 683.85,243.32 ; 658.66,243.32 664.39,249.05 ; 658.66,243.32 658.66,268.51 ; 658.66,268.51 664.39,262.78 ; 658.66,268.51 683.85,268.51 ; 664.39,249.05 664.39,262.78 ; 664.39,249.05 678.12,249.05 ; 664.39,262.78 678.12,262.78 ; 678.12,249.05 683.85,243.32 ; 678.12,249.05 678.12,262.78 ; 678.12,262.78 683.85,268.51 ; 683.85,243.32 683.85,268.51 ; 758.65,243.32 758.65,268.51 ; 758.65,243.32 764.39,249.05 ; 758.65,243.32 783.85,243.32 ; 758.65,268.51 764.39,262.78 ; 758.65,268.51 783.85,268.51 ; 764.39,249.05 764.39,262.78 ; 764.39,249.05 778.12,249.05 ; 764.39,262.78 778.12,262.78 ; 778.12,249.05 778.12,262.78 ; 778.12,249.05 783.85,243.32 ; 778.12,262.78 783.85,268.51 ; 783.85,243.32 783.85,268.51 ; 1173.23,-359.29 cw(c1173.23,-295.28) 1173.23,-231.27 ; 1173.23,-359.29 1232.29,-359.29 ; 1173.23,-231.27 1232.29,-231.27 ; 1232.29,-359.29 ccw(c1232.29,-295.28) 1232.29,-231.27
